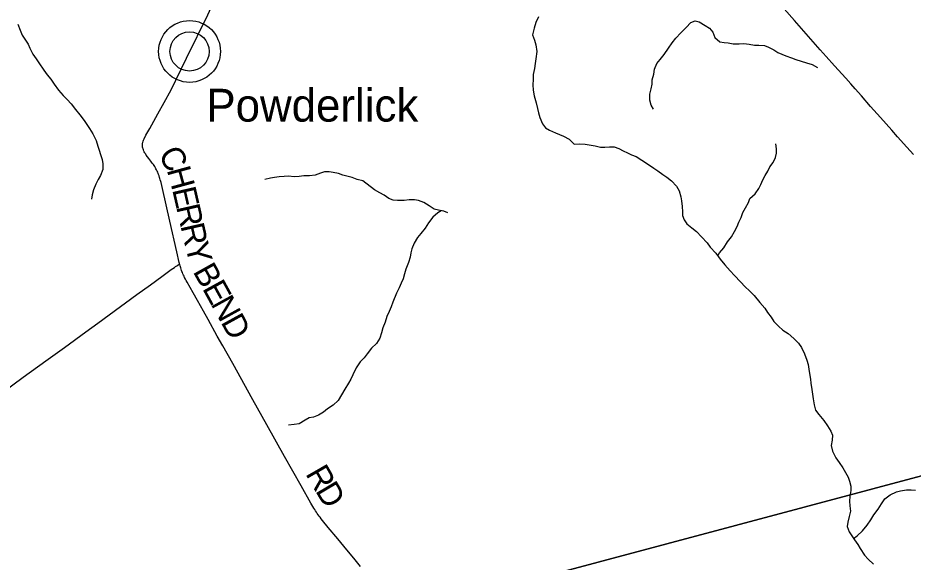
# Model space of a CAD drawing. Extents: x 1442749 to 1756758, y 235267 to 677782.
# Drawn here: x 1623834 to 1635226, y 527561 to 534483 of the extents above; entities that cross this region are included whole.
import ezdxf

# ---------------------------------------------------------------- set-up
doc = ezdxf.new("R2010")
doc.units = 0
for name, color, linetype in [('GM_X_County_Road', 7, 'Continuous'), ('GM_X_County_Road_Text', 7, 'Continuous'), ('GM_X_Major_River', 7, 'Continuous'), ('GM_X_Minor_River', 7, 'Continuous'), ('GM_X_Township', 7, 'Continuous'), ('GM_X_Township_Road', 7, 'Continuous'), ('GM_X_Unincorporated', 7, 'Continuous'), ('GM_X_Unincorporated_Location', 7, 'Continuous'), ('GM_X_Unincorporated_Text', 7, 'Continuous')]:
    doc.layers.add(name, color=color, linetype=linetype)

msp = doc.modelspace()

# ---------------------------------------------------------------- linework, layer by layer
at = {"layer": 'GM_X_County_Road'}
for points in [[(1625892, 531353), (1625890, 531360), (1625886, 531373), (1625855, 531507), (1625766, 531898), (1625719, 532106), (1625673, 532314), (1625655, 532388), (1625651, 532403), (1625645, 532423), (1625641, 532440), (1625637, 532453), (1625630, 532474), (1625625, 532491), (1625619, 532505), (1625613, 532520), (1625607, 532533), (1625598, 532550), (1625591, 532564), (1625585, 532576), (1625575, 532592), (1625567, 532604), (1625559, 532617), (1625547, 532633), (1625536, 532648), (1625526, 532662), (1625500, 532696), (1625468, 532738), (1625461, 532748), (1625454, 532759), (1625448, 532768), (1625442, 532779), (1625437, 532789), (1625431, 532804), (1625427, 532817), (1625424, 532827), (1625421, 532840), (1625420, 532853), (1625419, 532864), (1625420, 532877), (1625421, 532889), (1625423, 532900), (1625427, 532915), (1625431, 532926), (1625435, 532935), (1625439, 532945), (1625463, 532992), (1625512, 533078), (1625615, 533264), (1625696, 533407), (1625783, 533568), (1625844, 533692), (1625979, 533969), (1626041, 534092), (1626073, 534157), (1626163, 534343), (1626225, 534467), (1626299, 534623)], [(1628195, 527504), (1628126, 527589), (1627981, 527763), (1627904, 527856), (1627782, 528002), (1627709, 528092), (1627695, 528111), (1627679, 528132), (1627668, 528147), (1627655, 528164), (1627644, 528181), (1627634, 528195), (1627623, 528212), (1627612, 528229), (1627601, 528245), (1627563, 528310), (1627437, 528529), (1627228, 528905), (1627003, 529309), (1626825, 529626), (1626569, 530085), (1626441, 530311), (1626370, 530436), (1626255, 530645), (1626196, 530752), (1626119, 530889), (1626064, 530986), (1625986, 531123), (1625975, 531144), (1625966, 531161), (1625955, 531181), (1625948, 531197), (1625941, 531212), (1625934, 531226), (1625927, 531244), (1625922, 531258), (1625916, 531272), (1625911, 531287), (1625906, 531303), (1625902, 531316), (1625898, 531330), (1625894, 531346), (1625892, 531353)]]:
    msp.add_lwpolyline(points, dxfattribs=at)
at = {"layer": 'GM_X_Major_River'}
for points in [[(1630460, 534498), (1630426, 534426), (1630403, 534352), (1630383, 534266), (1630407, 534198), (1630426, 534140), (1630436, 534054), (1630425, 533964), (1630417, 533901), (1630407, 533841), (1630392, 533763), (1630390, 533701), (1630389, 533631), (1630393, 533563), (1630405, 533491), (1630428, 533404), (1630446, 533330), (1630460, 533274), (1630477, 533216), (1630509, 533136), (1630549, 533083), (1630601, 533057), (1630675, 533021), (1630779, 532980), (1630851, 532940), (1630911, 532875), (1630979, 532881), (1631051, 532876), (1631179, 532856), (1631249, 532837), (1631305, 532837), (1631362, 532843), (1631420, 532842), (1631482, 532820), (1631538, 532792), (1631590, 532767), (1631644, 532743), (1631704, 532719), (1631776, 532674), (1631846, 532626)], [(1631846, 532626), (1631927, 532571), (1631979, 532537), (1632041, 532493), (1632093, 532456), (1632153, 532410), (1632215, 532341), (1632249, 532283), (1632270, 532205), (1632278, 532155), (1632286, 532085), (1632291, 532018), (1632293, 531968), (1632311, 531916), (1632345, 531862), (1632410, 531811), (1632468, 531765), (1632532, 531697), (1632606, 531620), (1632644, 531568), (1632715, 531489), (1632773, 531413), (1632831, 531344), (1632897, 531266), (1632954, 531206), (1633028, 531125), (1633090, 531063), (1633146, 531010), (1633202, 530950), (1633277, 530865), (1633339, 530791), (1633373, 530737), (1633419, 530676), (1633452, 530622), (1633514, 530560), (1633570, 530511), (1633636, 530467), (1633708, 530406), (1633768, 530346), (1633806, 530290), (1633843, 530211), (1633873, 530131), (1633891, 530075), (1633900, 530015), (1633910, 529958), (1633920, 529886), (1633925, 529836), (1633939, 529758), (1633954, 529638), (1633968, 529563), (1633984, 529495), (1634025, 529439), (1634091, 529360), (1634137, 529296), (1634181, 529228), (1634200, 529175), (1634196, 529111), (1634182, 529045), (1634199, 528971), (1634245, 528889), (1634287, 528828), (1634332, 528762), (1634368, 528700), (1634398, 528641), (1634418, 528589), (1634433, 528527), (1634433, 528471), (1634423, 528397), (1634416, 528337), (1634422, 528277), (1634428, 528210), (1634413, 528140), (1634395, 528068), (1634386, 528014), (1634414, 527944), (1634446, 527894), (1634480, 527843), (1634522, 527785), (1634553, 527733), (1634609, 527650), (1634655, 527598), (1634721, 527534)]]:
    msp.add_lwpolyline(points, dxfattribs=at)
at = {"layer": 'GM_X_Minor_River'}
for points in [[(1631922, 533321), (1631891, 533371), (1631877, 533437), (1631878, 533512), (1631895, 533580), (1631906, 533640), (1631907, 533694), (1631926, 533766), (1631936, 533832), (1631967, 533902), (1632008, 533955), (1632057, 534019), (1632114, 534097), (1632161, 534168), (1632208, 534224), (1632271, 534293), (1632337, 534361), (1632396, 534426), (1632454, 534446), (1632504, 534431), (1632582, 534388), (1632636, 534352), (1632677, 534301), (1632705, 534234), (1632766, 534178), (1632820, 534171), (1632871, 534164), (1632937, 534154), (1633013, 534155), (1633073, 534156), (1633142, 534151), (1633210, 534136), (1633264, 534136), (1633334, 534133), (1633386, 534112), (1633452, 534076), (1633504, 534045), (1633556, 534020), (1633608, 534002), (1633678, 533975), (1633736, 533956), (1633802, 533933), (1633870, 533910), (1633940, 533892), (1634008, 533853)], [(1623833, 534403), (1623861, 534326), (1623890, 534264), (1623929, 534201), (1623963, 534148), (1623984, 534098), (1624026, 534021), (1624067, 533961), (1624099, 533910), (1624166, 533817), (1624207, 533758), (1624255, 533704), (1624294, 533641), (1624352, 533562), (1624411, 533495), (1624459, 533445), (1624512, 533388), (1624568, 533319), (1624621, 533248), (1624678, 533179), (1624712, 533129), (1624745, 533076), (1624787, 533008), (1624830, 532925), (1624849, 532853), (1624869, 532802), (1624884, 532746), (1624905, 532683), (1624915, 532627), (1624914, 532553), (1624885, 532479), (1624856, 532427), (1624827, 532367), (1624794, 532294), (1624777, 532232), (1624769, 532178)], [(1632740, 531457), (1632762, 531494), (1632817, 531559), (1632866, 531633), (1632915, 531699), (1632954, 531766), (1632987, 531830), (1633010, 531886), (1633037, 531944), (1633061, 532008), (1633094, 532066), (1633133, 532133), (1633150, 532187), (1633215, 532245), (1633264, 532314), (1633287, 532366), (1633314, 532422), (1633344, 532478), (1633379, 532534), (1633404, 532590), (1633445, 532645), (1633476, 532709), (1633490, 532761), (1633487, 532817), (1633480, 532882)], [(1629307, 532002), (1629253, 532023), (1629185, 532039), (1629131, 532052), (1629067, 532093), (1628999, 532134), (1628933, 532161), (1628883, 532171), (1628815, 532168), (1628750, 532161), (1628664, 532160), (1628610, 532166), (1628556, 532187), (1628494, 532228), (1628442, 532260), (1628372, 532295), (1628225, 532409), (1628151, 532428), (1628087, 532453), (1628035, 532464), (1627969, 532484), (1627915, 532503), (1627844, 532518), (1627794, 532527), (1627734, 532523), (1627684, 532506), (1627615, 532482), (1627545, 532473), (1627472, 532474), (1627412, 532467), (1627348, 532463), (1627277, 532468), (1627223, 532465), (1627157, 532460), (1627100, 532452), (1627050, 532445), (1626978, 532429)], [(1629219, 532031), (1629176, 532005), (1629115, 531948), (1629060, 531878), (1629015, 531809), (1628960, 531741), (1628921, 531689), (1628878, 531616), (1628847, 531546), (1628835, 531494), (1628826, 531440), (1628803, 531372), (1628770, 531286), (1628755, 531228), (1628736, 531164), (1628711, 531108), (1628687, 531050), (1628654, 530982), (1628604, 530866), (1628583, 530807), (1628560, 530747), (1628530, 530685), (1628507, 530613), (1628478, 530539), (1628459, 530477), (1628438, 530409), (1628397, 530341), (1628334, 530282), (1628277, 530210), (1628240, 530158), (1628189, 530107), (1628140, 530033), (1628097, 529945), (1628072, 529888), (1628043, 529836), (1627996, 529762), (1627951, 529690), (1627908, 529617), (1627845, 529559), (1627774, 529510), (1627723, 529470), (1627661, 529431), (1627594, 529405), (1627540, 529394), (1627489, 529366), (1627414, 529321), (1627350, 529312), (1627278, 529303)], [(1634467, 527862), (1634513, 527897), (1634584, 527957), (1634643, 528032), (1634688, 528100), (1634727, 528162), (1634782, 528233), (1634825, 528303), (1634868, 528365), (1634935, 528416), (1635014, 528453), (1635066, 528469), (1635142, 528480), (1635201, 528479), (1635259, 528477)]]:
    msp.add_lwpolyline(points, dxfattribs=at)
at = {"layer": 'GM_X_Township'}
for points in [[(1653261, 533457), (1649470, 532440), (1648625, 532214), (1643929, 530963), (1641622, 530343), (1638146, 529408), (1628661, 526876), (1619669, 524461), (1619911, 527377), (1620636, 536103), (1621013, 540634), (1621259, 543594), (1622672, 541854), (1633902, 542962), (1635524, 544621), (1639325, 548457), (1640433, 549458), (1640924, 550208), (1643512, 554247), (1643852, 554569), (1644396, 554944), (1644898, 555254)], [(1655741, 500852), (1648788, 495779), (1648023, 495203), (1647406, 496053), (1644427, 500259), (1642919, 502379), (1641006, 505069), (1637287, 510492), (1634462, 514529), (1632004, 518073), (1630779, 518715), (1629985, 519130), (1624968, 521723), (1619669, 524461), (1628661, 526876), (1638146, 529408), (1641622, 530343), (1643929, 530963), (1648625, 532214), (1649470, 532440), (1653261, 533457)]]:
    msp.add_lwpolyline(points, dxfattribs=at)
at = {"layer": 'GM_X_Township_Road'}
for points in [[(1635230, 532744), (1635147, 532837), (1635027, 532972), (1634955, 533053), (1634811, 533215), (1634685, 533357), (1634569, 533491), (1634489, 533579), (1634433, 533643), (1634371, 533715), (1634228, 533873), (1634122, 533994), (1634045, 534079), (1633717, 534450), (1633585, 534597)], [(1623504, 529622), (1623901, 529912), (1624191, 530122), (1624425, 530291), (1624698, 530491), (1624849, 530600), (1624995, 530707), (1625348, 530963), (1625520, 531089), (1625664, 531193), (1625786, 531282), (1625805, 531296), (1625826, 531310), (1625841, 531320), (1625856, 531330), (1625870, 531339), (1625892, 531353)]]:
    msp.add_lwpolyline(points, dxfattribs=at)
at = {"layer": 'GM_X_Unincorporated'}
for radius in [393, 249]:
    msp.add_circle((1626018, 534056), radius, dxfattribs=at)
at = {"layer": 'GM_X_Unincorporated_Location'}
msp.add_line((1626018, 534056), (1626018, 534056), dxfattribs=at)

# ---------------------------------------------------------------- texts
at = {"layer": 'GM_X_County_Road_Text'}
for s, rotation, p in [('C', 299.6631, (1625613, 532747)), ('H', 285.3174, (1625727, 532551)), ('E', 282.87, (1625796, 532300)), ('R', 282.8378, (1625846, 532081)), ('R', 282.8449, (1625901, 531840)), ('Y', 284.4269, (1625958, 531591)), ('B', 299.2044, (1626055, 531258)), ('E', 298.7928, (1626175, 531043)), ('N', 298.7927, (1626283, 530846)), ('D', 298.7953, (1626410, 530615)), ('R', 299.8833, (1627488, 528686)), ('D', 300.7351, (1627613, 528469))]:
    msp.add_text(s, height=300, rotation=rotation, dxfattribs=at).set_placement(p)
at = {"layer": 'GM_X_Unincorporated_Text'}
msp.add_text('Powderlick', height=417, rotation=0, dxfattribs=at).set_placement((1626233, 533164))

doc.saveas('drawing.dxf')
